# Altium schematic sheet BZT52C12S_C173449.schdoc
size 127 x 101 mm
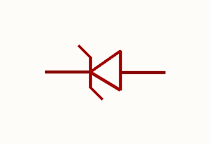
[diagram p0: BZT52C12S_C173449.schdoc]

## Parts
D?  bzt52c12s_c173449  [SOD-323_L1.8-W1.3-LS2.5-RD]  (value not drawn)

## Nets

Not connected (* = marked no-connect by the designer): D? 1 2

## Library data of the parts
D? = bzt52c12s_c173449: 二极管配置:1个独立式;稳压值(标称值):12V;稳压值(范围):11.4V~12.7V;耗散功率(Pd):200mW;; Manufacturer: MDD(辰达半导体); AddInBom: yes; ModelId: db63db13d9e342eb939127d413d6200b; ModelTransform: 104.3305,51.181,0,0,0,0,0,-0.004,0; Diode Configuration: 1个独立式; Zener Voltage(Nom): 12V; Reverse Leakage Current (Ir): 100nA@9V; Pd - Power Dissipation: 200mW; Impedance(Zzt): 35Ω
